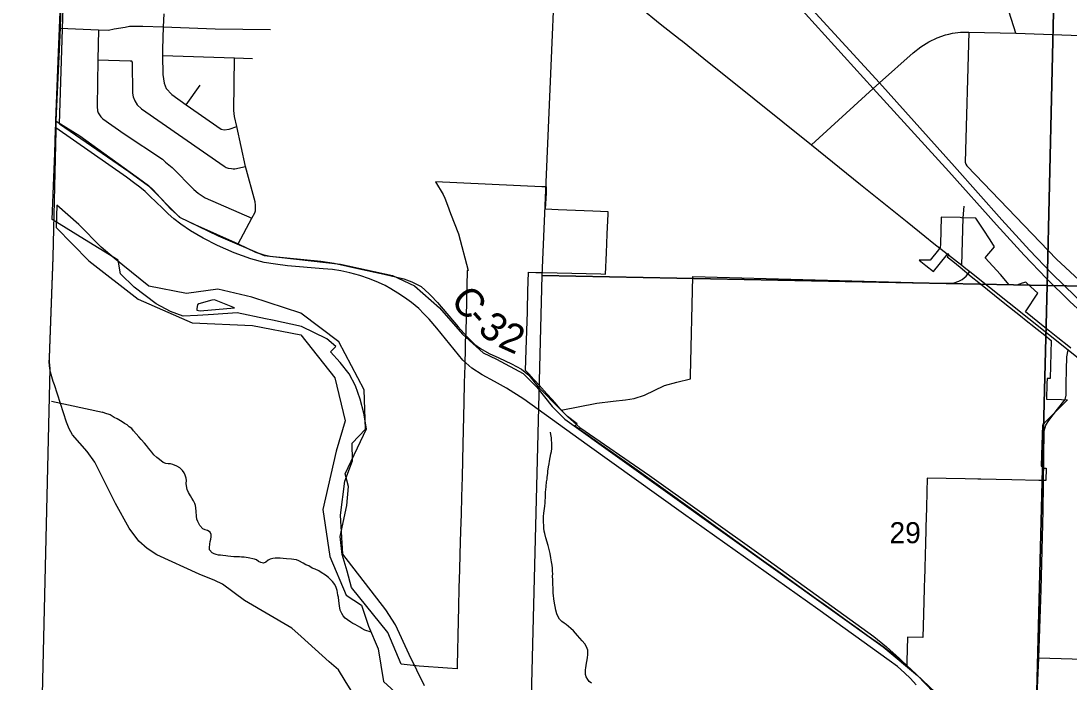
# Model space of a CAD drawing. Extents: x -7.5 to 26.5, y 3.5 to 25.5.
# Drawn here: x -5.3 to -3.216, y 20.391 to 21.705 of the extents above; entities that cross this region are included whole.
import ezdxf

# ---------------------------------------------------------------- set-up
doc = ezdxf.new("R2010")
doc.units = 0
for name, color, linetype in [('GM_X_City_Street', 7, 'Continuous'), ('GM_X_Corporation', 7, 'Continuous'), ('GM_X_County_Road', 7, 'Continuous'), ('GM_X_County_Road_Text', 7, 'Continuous'), ('GM_X_Interstate_Route', 7, 'Continuous'), ('GM_X_Minor_River', 7, 'Continuous'), ('GM_X_Rail_Line', 7, 'Continuous'), ('GM_X_Section_Text', 7, 'Continuous'), ('GM_X_Township_Road', 7, 'Continuous'), ('GM_X_US_Route', 7, 'Continuous')]:
    doc.layers.add(name, color=color, linetype=linetype)

msp = doc.modelspace()

# ---------------------------------------------------------------- linework, layer by layer
at = {"layer": 'GM_X_City_Street'}
for p, q in [((-4.9717, 21.5382), (-4.9437, 21.5768)), ((-3.4267, 21.3131), (-3.4248, 21.3367)), ((-3.2417, 21.2312), (-3.1468, 21.1433))]:
    msp.add_line(p, q, dxfattribs=at)
for points in [[(-5.0161, 21.7187), (-5.0173, 21.6931), (-5.0192, 21.6484), (-5.019, 21.6362), (-5.0182, 21.5986), (-5.0154, 21.581), (-5.0119, 21.5703), (-5.0005, 21.5585), (-4.9717, 21.5382), (-4.9022, 21.4895), (-4.8962, 21.4882), (-4.8863, 21.4894), (-4.8713, 21.4949)], [(-5.2221, 21.6906), (-5.1463, 21.6869), (-5.1262, 21.6862), (-5.1147, 21.6888), (-5.0929, 21.6927), (-5.0845, 21.6943), (-5.0579, 21.6946), (-5.0173, 21.6931), (-4.9139, 21.6894), (-4.8042, 21.6878)], [(-5.1463, 21.6869), (-5.1472, 21.6275), (-5.1486, 21.5348), (-5.1481, 21.5261), (-5.1468, 21.5219), (-5.1414, 21.5139), (-5.1373, 21.5101), (-5.095, 21.4802), (-5.0188, 21.4298), (-5.0127, 21.4243), (-4.9994, 21.4132), (-4.9565, 21.37), (-4.9481, 21.3626), (-4.9344, 21.353), (-4.8415, 21.3126)], [(-5.019, 21.6362), (-4.8755, 21.6312), (-4.8399, 21.6304)], [(-4.8682, 21.2617), (-4.8415, 21.3126), (-4.8356, 21.3235), (-4.8343, 21.3275), (-4.8338, 21.3314), (-4.8339, 21.3386), (-4.8349, 21.3451), (-4.8542, 21.4153), (-4.8713, 21.4949), (-4.8756, 21.5148), (-4.8774, 21.5267), (-4.8755, 21.6312)], [(-5.1472, 21.6275), (-5.083, 21.6258), (-5.0807, 21.6254), (-5.0802, 21.625), (-5.0798, 21.6243), (-5.0793, 21.6223), (-5.0786, 21.561), (-5.077, 21.5538), (-5.0742, 21.5461), (-5.0692, 21.5379), (-5.0607, 21.5304), (-4.8966, 21.4163), (-4.8924, 21.4137), (-4.8884, 21.4123), (-4.8815, 21.4112), (-4.8785, 21.411), (-4.8748, 21.411), (-4.8542, 21.4153)]]:
    msp.add_lwpolyline(points, dxfattribs=at)
at = {"layer": 'GM_X_Corporation'}
for points in [[(-4.2212, 22.2025), (-3.2367, 22.18), (-3.2602, 21.1789), (-4.2641, 21.1987)], [(-3.2367, 22.18), (-2.2479, 22.1217), (-2.268, 21.1618), (-3.2602, 21.1789)], [(-4.2641, 21.1987), (-3.2602, 21.1789), (-3.2852, 20.1896), (-4.2892, 20.2036)], [(-3.2602, 21.1789), (-2.268, 21.1618), (-2.2948, 20.1631), (-3.2852, 20.1896)]]:
    msp.add_lwpolyline(points, close=True, dxfattribs=at)
for points in [[(-3.213, 21.0546), (-3.2171, 21.0578), (-3.2385, 21.075), (-3.2551, 21.0882), (-3.2644, 21.0957), (-3.3029, 21.1265), (-3.2784, 21.1638), (-3.3, 21.1831), (-3.3027, 21.1855), (-3.3094, 21.1833), (-3.3206, 21.1797), (-3.3354, 21.1799), (-3.3388, 21.1839), (-3.353, 21.201), (-3.383, 21.2341), (-3.3645, 21.2559), (-3.3732, 21.2695), (-3.3871, 21.2911), (-3.4016, 21.3127), (-3.4016, 21.3128), (-3.43, 21.3137), (-3.4327, 21.3138), (-3.4706, 21.315), (-3.4723, 21.2612), (-3.4725, 21.2541), (-3.476, 21.2497), (-3.4927, 21.229), (-3.5144, 21.2295), (-3.501, 21.2187), (-3.4859, 21.2066), (-3.4611, 21.2378), (-3.4576, 21.2423), (-3.4554, 21.2405), (-3.4589, 21.236), (-3.4478, 21.2271), (-3.433, 21.2153), (-3.4111, 21.197), (-3.396, 21.185), (-3.3472, 21.146), (-3.3098, 21.116), (-3.3084, 21.1149), (-3.28, 21.0922), (-3.2648, 21.08), (-3.2519, 21.0697), (-3.2538, 20.9938), (-3.2602, 20.9939), (-3.2603, 20.9842), (-3.2603, 20.9833), (-3.261, 20.9529), (-3.2314, 20.9521), (-3.2198, 20.9519), (-3.2605, 20.9103), (-3.2695, 20.9011), (-3.2711, 20.8423), (-3.2717, 20.8199), (-3.2677, 20.8198), (-3.2678, 20.8161), (-3.2622, 20.816), (-3.2628, 20.7911), (-3.2729, 20.7914), (-3.2768, 20.7915), (-3.3305, 20.7925), (-3.3613, 20.7931), (-3.3921, 20.7937), (-3.398, 20.7938), (-3.4227, 20.7943), (-3.4983, 20.7956), (-3.4991, 20.7683), (-3.4999, 20.7373), (-3.4999, 20.7363), (-3.5004, 20.7181), (-3.501, 20.6979), (-3.5013, 20.6856), (-3.5016, 20.6733), (-3.502, 20.6609), (-3.5023, 20.6486), (-3.5026, 20.6363), (-3.503, 20.624), (-3.5033, 20.6117), (-3.5037, 20.5994), (-3.5043, 20.5768), (-3.5056, 20.5259), (-3.5069, 20.479), (-3.5377, 20.4798), (-3.539, 20.4315), (-3.5392, 20.4233), (-3.5763, 20.4534), (-3.5787, 20.4553), (-3.5983, 20.4694), (-3.6171, 20.4828), (-3.6352, 20.4958), (-3.6529, 20.5085), (-3.6575, 20.5118), (-3.6897, 20.5349), (-3.7034, 20.5447), (-3.7203, 20.5568), (-3.7902, 20.6069), (-3.8088, 20.62), (-3.8237, 20.6309), (-3.958, 20.7278), (-3.9791, 20.7432), (-4.0796, 20.8152), (-4.1646, 20.8747), (-4.1744, 20.8818), (-4.1844, 20.889), (-4.187, 20.8908), (-4.1892, 20.8925), (-4.1996, 20.9), (-4.1994, 20.9002), (-4.1946, 20.9041), (-4.2137, 20.9184), (-4.2178, 20.9227), (-4.2281, 20.9339), (-4.2349, 20.9414), (-4.2438, 20.9516), (-4.2549, 20.9638), (-4.2703, 20.9808), (-4.2873, 20.9996), (-4.2881, 21.0006), (-4.2969, 21.0102), (-4.2957, 21.0513), (-4.2935, 21.1265), (-4.2935, 21.1283), (-4.2934, 21.1301), (-4.2924, 21.1678), (-4.2913, 21.2052), (-4.2767, 21.2048), (-4.2628, 21.2045), (-4.2344, 21.2039), (-4.1475, 21.202), (-4.138, 21.2017), (-4.1363, 21.2435), (-4.1347, 21.2812), (-4.133, 21.3212), (-4.1329, 21.3255), (-4.1636, 21.3268), (-4.1975, 21.3282), (-4.2321, 21.3296), (-4.2572, 21.3307), (-4.2557, 21.3627), (-4.2552, 21.3747), (-4.2649, 21.3752), (-4.4764, 21.385), (-4.4609, 21.3601), (-4.4577, 21.3525), (-4.4524, 21.3387), (-4.4461, 21.3219), (-4.4307, 21.2814), (-4.4109, 21.2084), (-4.4132, 21.2085), (-4.4161, 21.0863), (-4.4164, 21.0754), (-4.4169, 21.0693), (-4.4173, 21.0398), (-4.4175, 21.0348), (-4.4179, 21.0199), (-4.4188, 20.9854), (-4.4198, 20.9466), (-4.4216, 20.8635), (-4.4225, 20.8311), (-4.4233, 20.7987), (-4.4244, 20.7589), (-4.4253, 20.7244), (-4.4263, 20.6912), (-4.4275, 20.6451), (-4.4284, 20.6136), (-4.4295, 20.5776), (-4.4305, 20.5394), (-4.431, 20.5122), (-4.4331, 20.4237), (-4.4333, 20.4167), (-4.4522, 20.4182), (-4.4708, 20.4196), (-4.49, 20.421), (-4.5087, 20.4224), (-4.5446, 20.4262), (-4.571, 20.4889), (-4.643, 20.5784), (-4.652, 20.611), (-4.6539, 20.618), (-4.6619, 20.6439), (-4.6654, 20.68), (-4.6524, 20.7417), (-4.6493, 20.7794), (-4.6555, 20.8043), (-4.6136, 20.8938), (-4.6184, 20.9248), (-4.6259, 20.9531), (-4.6355, 20.9794), (-4.6477, 21.0031), (-4.6657, 21.0257), (-4.6852, 21.0469), (-4.6745, 21.0575), (-4.6919, 21.0729), (-4.7423, 21.0974), (-4.8004, 21.1098), (-4.8142, 21.1127), (-4.8704, 21.1243), (-4.9175, 21.1215), (-4.9491, 21.1195), (-4.9778, 21.1178), (-5.0032, 21.1269), (-5.0317, 21.1424), (-5.0753, 21.1756), (-5.1022, 21.2023), (-5.1073, 21.2291), (-5.1825, 21.2757), (-5.2383, 21.3103), (-5.2351, 21.3935), (-5.2332, 21.4422), (-5.2315, 21.4887), (-5.2311, 21.499), (-5.2307, 21.5072), (-5.2255, 21.6421), (-5.2193, 21.8036)], [(-5.2204, 21.7606), (-5.2223, 21.6911), (-5.2307, 21.5062), (-5.2312, 21.4872), (-5.2369, 21.235), (-5.244, 21.0357), (-5.2442, 21.0272), (-5.2438, 21.0206), (-5.2429, 21.0142), (-5.2848, 19.2392), (-5.3003, 18.6476)], [(-5.2204, 21.7606), (-5.2223, 21.6911), (-5.2307, 21.5062), (-5.2312, 21.4872), (-5.2369, 21.235), (-5.244, 21.0357), (-5.2442, 21.0272), (-5.2438, 21.0206), (-5.2429, 21.0142), (-5.2848, 19.2392), (-4.6686, 19.2237), (-4.08, 19.2088), (-3.3198, 19.1896), (-3.3166, 19.1895), (-2.696, 19.1768)]]:
    msp.add_lwpolyline(points, dxfattribs=at)
at = {"layer": 'GM_X_County_Road'}
for p, q in [((-5.2304, 21.5057), (-5.2221, 21.6906)), ((-5.231, 21.4867), (-5.2304, 21.5057)), ((-3.4851, 21.2627), (-3.4298, 21.2193)), ((-3.4298, 21.2193), (-3.4218, 21.213)), ((-3.4218, 21.213), (-3.4139, 21.2066)), ((-3.4139, 21.2066), (-3.2185, 21.0507))]:
    msp.add_line(p, q, dxfattribs=at)
for points in [[(-5.2221, 21.6906), (-5.2201, 21.7601), (-5.2104, 22.0317)], [(-3.3225, 21.6802), (-3.3837, 21.875), (-3.4084, 21.9498), (-3.4271, 22.0107), (-3.4288, 22.0164)], [(-4.1097, 21.7644), (-4.1035, 21.7594), (-4.07, 21.7319), (-4.0292, 21.6988), (-3.9899, 21.668), (-3.9853, 21.6643)], [(-3.7287, 21.4585), (-3.6059, 21.5704), (-3.5932, 21.5815), (-3.5262, 21.6412), (-3.5114, 21.6531), (-3.4951, 21.6632), (-3.4789, 21.6709), (-3.4623, 21.6769), (-3.4556, 21.6785)], [(-3.4556, 21.6785), (-3.448, 21.6803), (-3.4322, 21.6823), (-3.4158, 21.6823)], [(-3.4158, 21.6823), (-3.3225, 21.6802), (-3.0839, 21.6717), (-3.0507, 21.6697)], [(-3.9853, 21.6643), (-3.9321, 21.6217), (-3.8996, 21.5959), (-3.7287, 21.4585)], [(-5.2304, 21.5057), (-5.1832, 21.4767), (-5.0594, 21.3871), (-5.0469, 21.3775), (-5.0376, 21.3692), (-5.0029, 21.3311), (-4.9835, 21.3138), (-4.9548, 21.3002), (-4.8682, 21.2617), (-4.8342, 21.2454), (-4.8195, 21.2402), (-4.8057, 21.2374), (-4.7042, 21.2272), (-4.6775, 21.2231), (-4.6304, 21.213), (-4.5785, 21.2014), (-4.5393, 21.1921), (-4.5229, 21.1859), (-4.5046, 21.1766), (-4.4884, 21.162), (-4.4863, 21.1598)], [(-3.7287, 21.4585), (-3.6308, 21.3796), (-3.5383, 21.3057), (-3.5033, 21.277), (-3.4851, 21.2627)], [(-5.2339, 20.9816), (-5.236, 20.9881), (-5.2413, 21.0066), (-5.2426, 21.0137), (-5.2435, 21.0201), (-5.244, 21.0267), (-5.2438, 21.0352), (-5.2366, 21.2345)], [(-4.2263, 20.9308), (-4.1556, 20.9451), (-4.1232, 20.9493), (-4.0981, 20.9515), (-4.0813, 20.9544), (-4.0603, 20.9609), (-4.0205, 20.9804), (-3.9964, 20.9868), (-3.9689, 20.9931), (-3.9688, 20.9991), (-3.9646, 21.1967), (-3.4783, 21.1836), (-3.4523, 21.1833), (-3.4446, 21.1844), (-3.4359, 21.1874), (-3.4291, 21.1908), (-3.421, 21.1976), (-3.4139, 21.2066)], [(-4.4863, 21.1598), (-4.4856, 21.159), (-4.4723, 21.1451), (-4.4311, 21.0967), (-4.4133, 21.0769)], [(-4.4133, 21.0769), (-4.4106, 21.074), (-4.3982, 21.0618), (-4.3867, 21.0538), (-4.3696, 21.0438), (-4.3505, 21.0352), (-4.3248, 21.0229), (-4.305, 21.0128), (-4.2903, 21.0005), (-4.2724, 20.9783), (-4.2263, 20.9308), (-4.2131, 20.9178), (-4.1891, 20.8965), (-4.0509, 20.8015), (-3.8286, 20.643)], [(-3.2216, 21.011), (-3.2209, 21.0368), (-3.2185, 21.0507)], [(-3.2185, 21.0507), (-3.1736, 21.0152), (-2.9086, 20.8072), (-2.8624, 20.7707), (-2.8508, 20.7615)], [(-3.2224, 20.9618), (-3.2224, 20.97), (-3.2224, 20.9833), (-3.2216, 21.011)], [(-4.6407, 20.3686), (-4.6554, 20.393), (-4.6691, 20.4147), (-4.6875, 20.4305), (-4.7431, 20.4813), (-4.7619, 20.4979), (-4.8559, 20.5527), (-4.8996, 20.5849), (-4.9149, 20.5926), (-4.9459, 20.6054), (-5.0303, 20.6435), (-5.0493, 20.6559), (-5.0662, 20.6705), (-5.0851, 20.6962), (-5.1122, 20.7453), (-5.1537, 20.8279), (-5.1686, 20.8489), (-5.1978, 20.8821), (-5.2042, 20.8939), (-5.2097, 20.9073), (-5.2339, 20.9816)], [(-3.2809, 20.3346), (-3.2767, 20.4388), (-3.2721, 20.5738), (-3.2679, 20.7309), (-3.2662, 20.8902), (-3.2627, 20.9014), (-3.2568, 20.9105), (-3.2392, 20.9329), (-3.2245, 20.9523), (-3.2224, 20.9608), (-3.2224, 20.9618)], [(-3.8286, 20.643), (-3.8147, 20.6331), (-3.6049, 20.4814), (-3.5794, 20.4604), (-3.5533, 20.4372), (-3.5482, 20.4323)], [(-3.5482, 20.4323), (-3.5206, 20.4061), (-3.4824, 20.3706), (-3.4713, 20.3604), (-3.4463, 20.3354), (-3.4442, 20.3333), (-3.4379, 20.3278), (-3.4327, 20.3249), (-3.4241, 20.3224), (-3.353, 20.3275), (-3.2809, 20.3346)], [(-3.2767, 20.4388), (-2.8797, 20.4266), (-2.7425, 20.4238)]]:
    msp.add_lwpolyline(points, dxfattribs=at)
at = {"layer": 'GM_X_Interstate_Route'}
for points in [[(-4.1567, 22.202), (-4.0594, 22.096), (-3.9428, 21.9662), (-3.7871, 21.7934), (-3.5932, 21.5815), (-3.4445, 21.4153), (-3.3498, 21.3091), (-3.2949, 21.249), (-3.2506, 21.2025), (-3.2037, 21.1569), (-3.1576, 21.1144), (-3.1133, 21.0758), (-2.9944, 20.9805), (-2.7725, 20.8074), (-2.7357, 20.7786), (-2.6558, 20.7178), (-2.5166, 20.6214)], [(-3.9713, 21.9758), (-3.9537, 21.9563), (-3.798, 21.7835), (-3.6059, 21.5704), (-3.4554, 21.4053), (-3.3607, 21.2992), (-3.3058, 21.2391), (-3.2615, 21.1926), (-3.2146, 21.147), (-3.1685, 21.1044), (-3.1242, 21.0658), (-3.0115, 20.9737), (-2.7821, 20.7947), (-2.748, 20.7669)]]:
    msp.add_lwpolyline(points, dxfattribs=at)
at = {"layer": 'GM_X_Minor_River'}
msp.add_line((-5.229, 21.3387), (-5.2302, 21.2945), dxfattribs=at)
for points in [[(-4.4977, 20.3831), (-4.5285, 20.4455), (-4.5556, 20.5047), (-4.5748, 20.5341), (-4.6603, 20.6446), (-4.6649, 20.7226), (-4.6566, 20.7899), (-4.6414, 20.8301), (-4.6416, 20.8654), (-4.6154, 20.8931), (-4.6177, 20.9717), (-4.6681, 21.0669), (-4.7437, 21.124), (-4.8412, 21.156), (-4.9089, 21.1715), (-4.9709, 21.163), (-5.0462, 21.1776), (-5.1151, 21.2334), (-5.141, 21.2554), (-5.1855, 21.2999), (-5.229, 21.3387)], [(-5.2302, 21.2945), (-5.1656, 21.2277), (-5.067, 21.152), (-4.9597, 21.105), (-4.8402, 21.0994), (-4.7441, 21.0811), (-4.6765, 20.9954), (-4.6558, 20.9098), (-4.6734, 20.8496), (-4.6998, 20.7334), (-4.6865, 20.6404), (-4.6539, 20.5632), (-4.623, 20.5434), (-4.6091, 20.5014)], [(-4.8758, 21.1343), (-4.9152, 21.1505), (-4.9209, 21.1499), (-4.9464, 21.1425), (-4.9491, 21.1403), (-4.9505, 21.1332), (-4.9506, 21.1297), (-4.9438, 21.1284)], [(-4.9438, 21.1284), (-4.8758, 21.1343)], [(-5.2393, 20.9492), (-5.1379, 20.9273)], [(-5.0078, 20.8244), (-5.012, 20.8249), (-5.0176, 20.827), (-5.0246, 20.833), (-5.0305, 20.8373), (-5.036, 20.8425), (-5.0404, 20.8476), (-5.0466, 20.8558), (-5.051, 20.8608), (-5.0546, 20.8652), (-5.0612, 20.8726), (-5.0663, 20.8781), (-5.0766, 20.8898), (-5.0798, 20.8949), (-5.085, 20.8977), (-5.0894, 20.9017), (-5.0943, 20.9049), (-5.0991, 20.9077), (-5.1091, 20.9138), (-5.1151, 20.9166), (-5.1192, 20.9191), (-5.1233, 20.9219), (-5.1338, 20.9253), (-5.1379, 20.9273)], [(-4.1662, 20.3884), (-4.1703, 20.3916), (-4.1732, 20.3959), (-4.1768, 20.4009), (-4.1781, 20.4059), (-4.1778, 20.415), (-4.1773, 20.4192), (-4.1764, 20.4237), (-4.1759, 20.4283), (-4.1745, 20.4351), (-4.1739, 20.4396), (-4.1734, 20.4445), (-4.1732, 20.4495), (-4.1734, 20.454), (-4.1759, 20.4606), (-4.1795, 20.4664), (-4.1842, 20.4727), (-4.189, 20.4778), (-4.1937, 20.4832), (-4.1977, 20.4876), (-4.2017, 20.4926), (-4.2073, 20.497), (-4.2117, 20.5013), (-4.2161, 20.5049), (-4.2202, 20.5077), (-4.225, 20.5113), (-4.2294, 20.5156), (-4.2326, 20.5214), (-4.2347, 20.5265), (-4.2368, 20.5334), (-4.2384, 20.5407), (-4.2397, 20.5475), (-4.2409, 20.5559), (-4.2418, 20.5624), (-4.2421, 20.567), (-4.2422, 20.5731), (-4.2424, 20.5788), (-4.2426, 20.5841), (-4.2428, 20.5898), (-4.243, 20.5948), (-4.2432, 20.6005), (-4.243, 20.6062), (-4.2432, 20.6107), (-4.2434, 20.6168), (-4.2443, 20.6229), (-4.2452, 20.6294), (-4.2465, 20.6375), (-4.2484, 20.6463), (-4.2504, 20.6539), (-4.2524, 20.662), (-4.2565, 20.6773), (-4.2585, 20.6858), (-4.2598, 20.6908), (-4.2604, 20.6965), (-4.2609, 20.7026), (-4.2611, 20.7075), (-4.2617, 20.7136), (-4.2611, 20.7197), (-4.2605, 20.7261), (-4.2599, 20.7307), (-4.2588, 20.7405), (-4.2582, 20.7469), (-4.2577, 20.7614), (-4.2571, 20.7686), (-4.2566, 20.7727), (-4.256, 20.7796), (-4.2553, 20.7883), (-4.2543, 20.7939), (-4.2538, 20.7981), (-4.2528, 20.8049), (-4.2526, 20.8098), (-4.2512, 20.8185), (-4.2499, 20.8246), (-4.2493, 20.8295), (-4.2479, 20.837), (-4.2465, 20.8442), (-4.2456, 20.8491), (-4.245, 20.8552), (-4.2448, 20.8609), (-4.245, 20.8654), (-4.2456, 20.8719), (-4.2458, 20.8761), (-4.2471, 20.8826), (-4.2477, 20.8872)], [(-4.6041, 20.4895), (-4.6168, 20.4936), (-4.6224, 20.4972), (-4.6264, 20.4997), (-4.6313, 20.5025), (-4.6358, 20.5049), (-4.6402, 20.507), (-4.6443, 20.5094), (-4.6514, 20.5142), (-4.6555, 20.5174), (-4.6598, 20.5221), (-4.6623, 20.5267), (-4.6655, 20.5337), (-4.6667, 20.5421), (-4.6683, 20.5524), (-4.6688, 20.5593), (-4.6702, 20.5635), (-4.6712, 20.5685), (-4.6718, 20.5727), (-4.6735, 20.5784), (-4.6763, 20.5846), (-4.6806, 20.5904), (-4.685, 20.5948), (-4.6891, 20.5983), (-4.695, 20.6031), (-4.7036, 20.6087), (-4.7084, 20.6119), (-4.7151, 20.6152), (-4.7211, 20.6173), (-4.7278, 20.6217), (-4.7338, 20.6238), (-4.739, 20.627), (-4.7479, 20.6319), (-4.7528, 20.6336), (-4.7577, 20.6345), (-4.7626, 20.6351), (-4.7725, 20.6354), (-4.7793, 20.636), (-4.785, 20.6366), (-4.7899, 20.6371), (-4.7948, 20.6369), (-4.7998, 20.6363), (-4.8048, 20.635), (-4.809, 20.6329), (-4.8137, 20.6292), (-4.8184, 20.6267), (-4.8236, 20.628), (-4.8281, 20.6305), (-4.8322, 20.6333), (-4.8363, 20.6349), (-4.8487, 20.6377), (-4.8563, 20.6387), (-4.8616, 20.6392), (-4.8661, 20.6398), (-4.8714, 20.6396), (-4.8768, 20.6398), (-4.8828, 20.6403), (-4.8889, 20.6409), (-4.893, 20.6415), (-4.8987, 20.642), (-4.9036, 20.6426), (-4.9078, 20.6431), (-4.9119, 20.644), (-4.9161, 20.6453), (-4.9201, 20.6477), (-4.9253, 20.6536), (-4.9255, 20.6578), (-4.9245, 20.6646), (-4.9239, 20.6699), (-4.9226, 20.6748), (-4.9221, 20.6793), (-4.9223, 20.6839), (-4.924, 20.6885), (-4.9296, 20.6917), (-4.9338, 20.6934), (-4.939, 20.6951), (-4.9445, 20.7021), (-4.9488, 20.7095), (-4.9505, 20.7145), (-4.951, 20.7206), (-4.9519, 20.7294), (-4.9527, 20.737), (-4.9533, 20.7416), (-4.9547, 20.7458), (-4.9572, 20.7508), (-4.9604, 20.7559), (-4.9633, 20.7609), (-4.9673, 20.7675), (-4.9701, 20.7733), (-4.9714, 20.7806), (-4.9716, 20.7855), (-4.9714, 20.7916), (-4.972, 20.7962), (-4.9737, 20.8019), (-4.9758, 20.8062), (-4.979, 20.8113), (-4.9846, 20.8164), (-4.9901, 20.8196), (-4.9984, 20.8229), (-5.0033, 20.8242), (-5.0078, 20.8244)], [(-4.6091, 20.5014), (-4.5903, 20.4564), (-4.5796, 20.3917), (-4.5414, 20.3565), (-4.4626, 20.3304), (-4.3638, 20.3293), (-4.2472, 20.3158), (-4.1289, 20.296)]]:
    msp.add_lwpolyline(points, dxfattribs=at)
at = {"layer": 'GM_X_Rail_Line'}
msp.add_line((-5.2239, 21.5005), (-5.1999, 22.2339), dxfattribs=at)
for points in [[(-3.5203, 20.3848), (-3.5317, 20.3974), (-3.5433, 20.4092), (-3.5578, 20.4217), (-3.5738, 20.4335), (-3.7161, 20.5354), (-3.9827, 20.7252), (-4.1748, 20.8623), (-4.3008, 20.9527), (-4.3347, 20.9749), (-4.3591, 20.988), (-4.3834, 21.0013), (-4.404, 21.0147), (-4.4218, 21.0307), (-4.4734, 21.0941), (-4.4886, 21.112), (-4.4991, 21.1229), (-4.5094, 21.1329), (-4.5241, 21.1448), (-4.5376, 21.1549), (-4.5508, 21.1638), (-4.5646, 21.1721), (-4.5764, 21.1786), (-4.5894, 21.1851), (-4.6074, 21.1923), (-4.6268, 21.1988), (-4.6462, 21.2042), (-4.6644, 21.2081), (-4.6806, 21.2104), (-4.6996, 21.2123), (-4.7703, 21.2179), (-4.7944, 21.2211), (-4.8167, 21.2247), (-4.8432, 21.2319), (-4.8762, 21.2435), (-4.9095, 21.2584), (-4.938, 21.2727), (-4.9633, 21.2876), (-4.9825, 21.3008), (-4.9961, 21.3111), (-5.0078, 21.3212), (-5.019, 21.3325), (-5.0444, 21.3565), (-5.0536, 21.3655), (-5.0638, 21.3743), (-5.0737, 21.3819), (-5.0903, 21.3941), (-5.2311, 21.4924)], [(-5.2239, 21.5005), (-5.0857, 21.4052), (-5.0466, 21.3771), (-4.9853, 21.3149), (-4.908, 21.2775), (-4.8171, 21.2388), (-4.6653, 21.221), (-4.5619, 21.199), (-4.5178, 21.1785), (-4.4683, 21.1348), (-4.4223, 21.0819), (-4.3814, 21.045), (-4.3546, 21.0324), (-4.3015, 21.0037), (-4.2746, 20.977), (-4.2441, 20.9387), (-4.2187, 20.9133), (-3.5861, 20.4608), (-3.5178, 20.4035), (-3.4532, 20.3366)]]:
    msp.add_lwpolyline(points, dxfattribs=at)
at = {"layer": 'GM_X_Township_Road'}
msp.add_line((-3.4298, 21.2193), (-3.4267, 21.3131), dxfattribs=at)
for points in [[(-3.4158, 21.6823), (-3.4228, 21.4243), (-3.4218, 21.4201), (-3.4196, 21.4166)], [(-3.4196, 21.4166), (-3.4189, 21.4159), (-3.2417, 21.2312)]]:
    msp.add_lwpolyline(points, dxfattribs=at)
at = {"layer": 'GM_X_US_Route'}
msp.add_lwpolyline([(-3.9713, 21.9758), (-3.9537, 21.9563), (-3.798, 21.7835), (-3.6059, 21.5704), (-3.4554, 21.4053), (-3.3607, 21.2992), (-3.3058, 21.2391), (-3.2615, 21.1926), (-3.2146, 21.147), (-3.1685, 21.1044), (-3.1242, 21.0658), (-3.0115, 20.9737), (-2.7821, 20.7947), (-2.748, 20.7669)], dxfattribs=at)

# ---------------------------------------------------------------- texts
at = {"layer": 'GM_X_County_Road_Text'}
for s, rotation, p in [('C', 311.2255, (-4.4486, 21.1475)), ('-', 311.7736, (-4.4177, 21.1122)), ('3', 321.9752, (-4.3943, 21.0874)), ('2', 335.8194, (-4.3541, 21.0583))]:
    msp.add_text(s, height=0.0568, rotation=rotation, dxfattribs=at).set_placement(p)
at = {"layer": 'GM_X_Section_Text'}
msp.add_text('29', height=0.04186, rotation=0, dxfattribs=at).set_placement((-3.5734, 20.6666))

doc.saveas('drawing.dxf')
